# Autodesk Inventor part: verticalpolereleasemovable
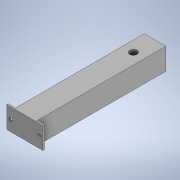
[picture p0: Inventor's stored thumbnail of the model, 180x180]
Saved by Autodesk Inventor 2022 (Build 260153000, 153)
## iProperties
Created: 2021-06
Part Number: verticalpolereleasemovable
Material: Generic
Document SubType Name: Modeling
Designer: Chimms
Density: 1 g/cm^3
Appearance: Default
Author: Chimms
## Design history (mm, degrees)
sketch "Sketch1"
  geometry: L1 (0, 0)-(30, 0); L2 (30, 0)-(30, 30); L3 (30, 30)-(0, 30); L4 (0, 30)-(0, 0)
  constraints: 8 end point, 2 parallel, 1 horizontal, 1 perpendicular
  dimensions: "d0" = 30 distance of L3.end L2.end; "d1" = 30 distance of L2.end L1.end
extrude "Extrusion1" new body sketch "Sketch1" distance "d2" = 180; taper "d3" = 0 deg
sketch "Sketch2"
  geometry: L1 (30, 0)-(0, 0) reference; C1 r 5 at (15, -30)
  constraints: 1 centre point
  dimensions: "d5" = 10 diameter of C1
extrude "Extrusion2" cut sketch "Sketch2" extent not by distance; stored distance "d6" = 0; taper "d7" = 0 deg
sketch "Sketch3"
  geometry: L1 (0, 30)-(0, 0) reference; L2 (0, 30)-(-10, 30); L3 (-10, 30)-(-10, 0); L4 (-10, 0)-(0, 0); L5 (0, 0)-(0, 30); 1 further point
  constraints: 8 end point, 2 parallel, 1 horizontal, 1 perpendicular
  dimensions: "d8" = 10 distance of L4.end L3.end
sketch "Sketch4"
  geometry: L1 (30, 0)-(30, 30) reference; L2 (30, 30)-(40, 30); L3 (40, 30)-(40, 0); L4 (40, 0)-(30, 0); L5 (30, 0)-(30, 30); C1 r 2.5 at (-5.466, 15); C2 r 2.5 at (35, 15); 2 further points
  constraints: 8 end point, 2 centre point, 2 parallel, 1 horizontal, 1 perpendicular
  dimensions: "d9" = 5 diameter of C1; "d10" = 10 distance of L3.end L4.end; "d11" = 5 diameter of C2
extrude "Extrusion3" join sketch "Sketch3" distance "d12" = 2; taper "d13" = 0 deg
extrude "Extrusion4" join sketch "Sketch4" distance "d14" = 2; taper "d15" = 0 deg
sketch "Sketch5"
  geometry: C1 r 2.5 at (-4.541, 15); 1 further point
  constraints: 1 centre point
  dimensions: "d16" = 5 diameter of C1
extrude "Extrusion5" cut sketch "Sketch5" extent not by distance; stored distance "d17" = 0; taper "d18" = 0 deg
body "Solid1"
